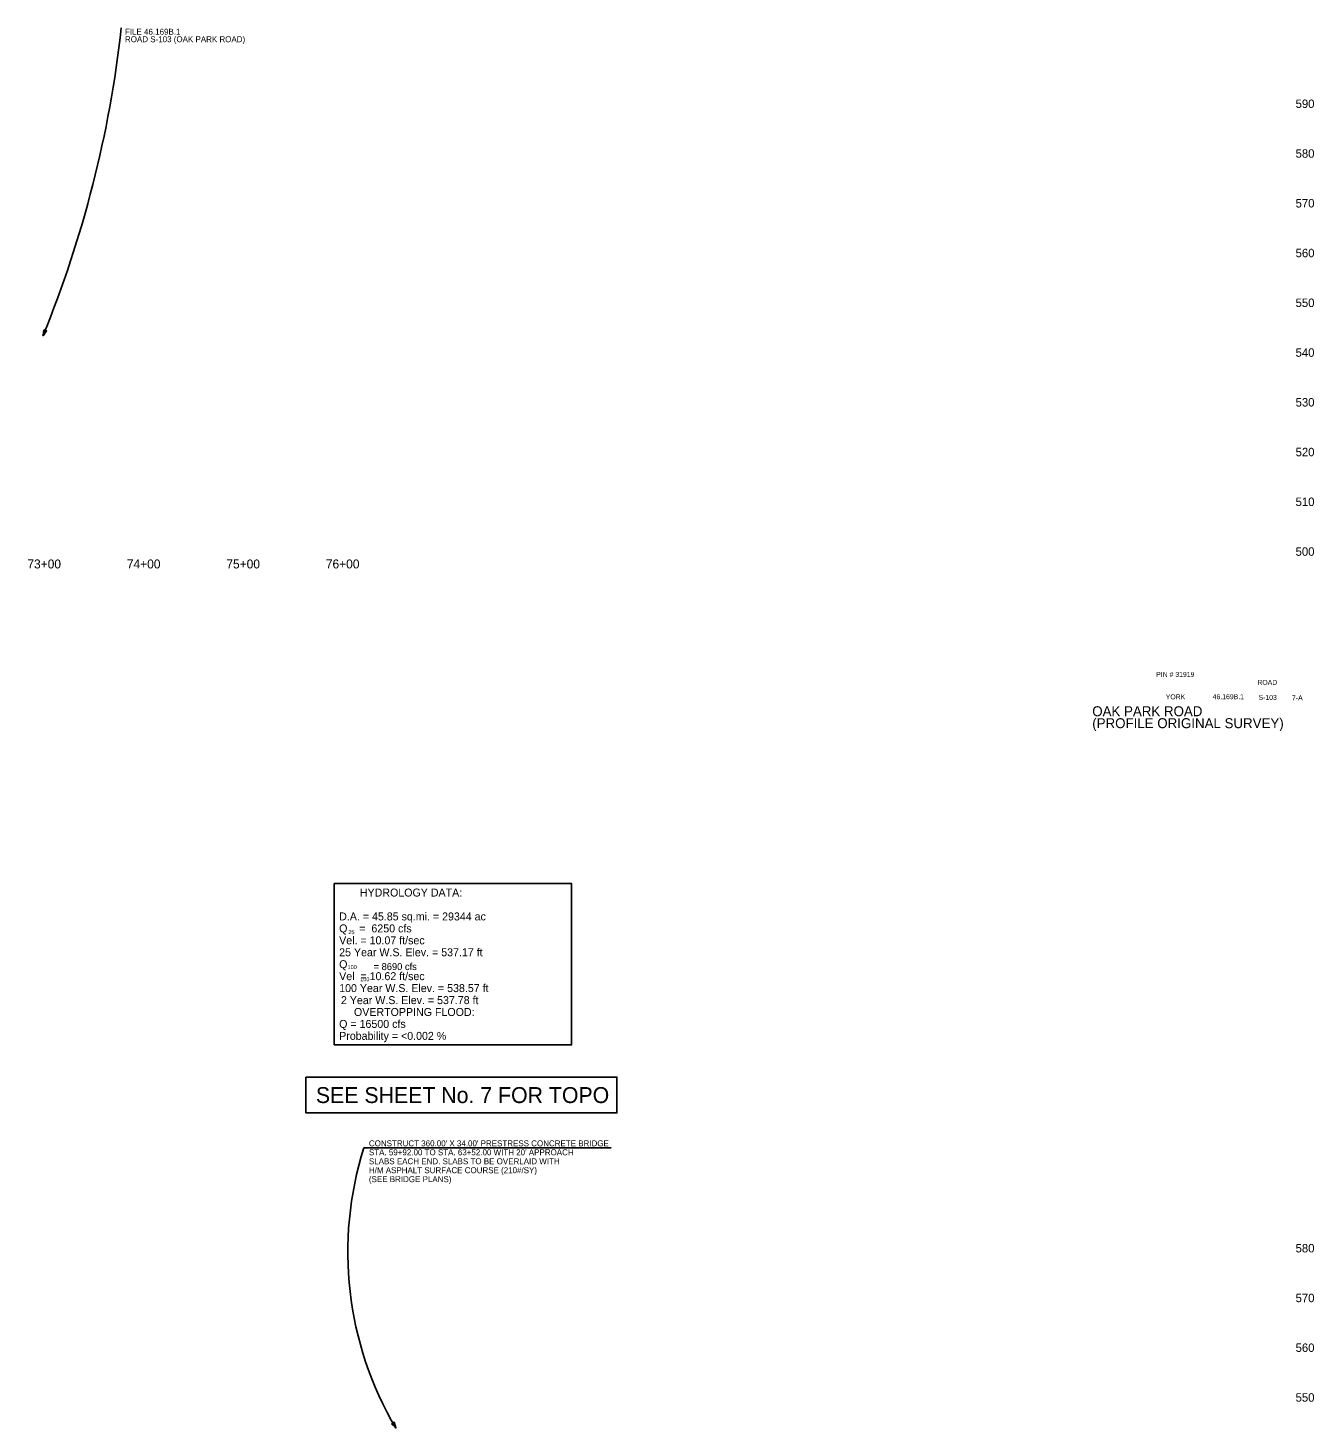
# Model space of a CAD drawing. Extents: x 1959560 to 1962161, y 1107485 to 1113134.
# Drawn here: x 1960869 to 1962161, y 1108922 to 1110328 of the extents above; entities that cross this region are included whole.
import ezdxf

# ---------------------------------------------------------------- set-up
doc = ezdxf.new("R2010")
doc.units = 0
for name, color, linetype in [('Level 21', 7, 'Continuous'), ('Level 29', 7, 'Continuous'), ('Level 41', 7, 'Continuous'), ('Level 42', 7, 'Continuous')]:
    doc.layers.add(name, color=color, linetype=linetype)

msp = doc.modelspace()

# ---------------------------------------------------------------- linework, layer by layer
at = {"layer": 'Level 21'}
msp.add_lwpolyline([(1960884.4, 1110025.3), (1960883.7, 1110019.3), (1960887.3, 1110024.1)], close=True, dxfattribs=at)
msp.add_arc((1959817.8, 1110455), 1151.5, 337.7677, 353.6912, dxfattribs=at)
at = {"layer": 'Level 29'}
msp.add_line((1961454.7, 1109203.2), (1961206.3, 1109203.2), dxfattribs=at)
msp.add_lwpolyline([(1961234.1, 1108925.9), (1961238.4, 1108921.7), (1961236.8, 1108927.4)], close=True, dxfattribs=at)
msp.add_arc((1961537.8, 1109098.4), 347.7, 162.463, 210.5549, dxfattribs=at)
at = {"layer": 'Level 41'}
for points in [[(1961176.4, 1109306.6), (1961415, 1109306.6), (1961415, 1109468.7), (1961176.4, 1109468.7)], [(1961148, 1109274.2), (1961460.6, 1109274.2), (1961460.6, 1109238.2), (1961148, 1109238.2)]]:
    msp.add_lwpolyline(points, close=True, dxfattribs=at)

# ---------------------------------------------------------------- texts
at = {"layer": 'Level 21'}
for s, p in [('FILE 46.169B.1', (1960966.1, 1110321.7)), ('ROAD S-103 (OAK PARK ROAD)', (1960966.1, 1110314.2))]:
    msp.add_text(s, height=6, dxfattribs=at).set_placement(p)
at = {"layer": 'Level 29'}
for s, p in [("CONSTRUCT 360.00' X 34.00' PRESTRESS CONCRETE BRIDGE", (1961211.3, 1109204.7)), ("STA. 59+92.00 TO STA. 63+52.00 WITH 20' APPROACH", (1961211.3, 1109195.7)), ('SLABS EACH END. SLABS TO BE OVERLAID WITH', (1961211.3, 1109186.7)), ('H/M ASPHALT SURFACE COURSE (210#/SY)', (1961211.3, 1109177.7)), ('(SEE BRIDGE PLANS)', (1961211.3, 1109168.7))]:
    msp.add_text(s, height=6, dxfattribs=at).set_placement(p)
at = {"layer": 'Level 41'}
for s, height, p in [('PIN # 31919', 5, (1962002.7, 1109676.4)), ('ROAD', 5, (1962104.4, 1109668.4)), ('YORK', 5, (1962012.3, 1109653.9)), ('46.169B.1', 5, (1962059.4, 1109654)), ('S-103', 5, (1962105.5, 1109653.3)), ('OAK PARK ROAD', 10, (1961938.4, 1109636.9)), ('7-A', 5, (1962139.2, 1109652.9)), ('(PROFILE ORIGINAL SURVEY)', 10, (1961938.4, 1109624.9)), ('       HYDROLOGY DATA:', 8, (1961181.4, 1109455.7)), ('D.A. = 45.85 sq.mi. = 29344 ac', 8, (1961181.4, 1109431.7)), ('Q    =  6250 cfs', 8, (1961181.4, 1109419.7)), (' 25', 4, (1961189.1, 1109417.9)), ('Vel. = 10.07 ft/sec', 8, (1961181.4, 1109407.7)), ('25 Year W.S. Elev. = 537.17 ft', 8, (1961181.4, 1109395.7)), ('Q', 8, (1961181.4, 1109383.7)), ('Vel  = 10.62 ft/sec', 8, (1961181.4, 1109371.7)), ('100', 4, (1961189.9, 1109382.8)), ('= 8690 cfs', 7, (1961216, 1109381.8)), ('100 Year W.S. Elev. = 538.57 ft', 8, (1961181.4, 1109359.7)), ('100', 4, (1961202.6, 1109370.6)), ('2 Year W.S. Elev. = 537.78 ft', 8, (1961183.2, 1109347.6)), ('     OVERTOPPING FLOOD:', 8, (1961181.4, 1109335.7)), ('Q = 16500 cfs', 8, (1961181.4, 1109323.7)), ('Probability = <0.002 %', 8, (1961181.4, 1109311.7)), ('SEE SHEET No. 7 FOR TOPO', 16, (1961158, 1109248.2))]:
    msp.add_text(s, height=height, dxfattribs=at).set_placement(p)
at = {"layer": 'Level 42'}
for s, height, p in [('590', 8.5, (1962142.8, 1110248.1)), ('580', 8.5, (1962142.8, 1110198.1)), ('570', 8.5, (1962142.8, 1110148.1)), ('560', 8.5, (1962142.8, 1110098.1)), ('550', 8.5, (1962142.8, 1110048.1)), ('540', 8.5, (1962142.8, 1109998.1)), ('530', 8.5, (1962142.8, 1109948.1)), ('520', 8.5, (1962142.8, 1109898.1)), ('510', 8.5, (1962142.8, 1109848.1)), ('500', 8.5, (1962142.8, 1109798.1)), ('73+00', 9, (1960868, 1109785.4)), ('74+00', 9, (1960968, 1109785.4)), ('75+00', 9, (1961068, 1109785.4)), ('76+00', 9, (1961168, 1109785.4)), ('580', 8.5, (1962142.8, 1109098.1)), ('570', 8.5, (1962142.8, 1109048.1)), ('560', 8.5, (1962142.8, 1108998.1)), ('550', 8.5, (1962142.8, 1108948.1))]:
    msp.add_text(s, height=height, dxfattribs=at).set_placement(p)

doc.saveas('drawing.dxf')
